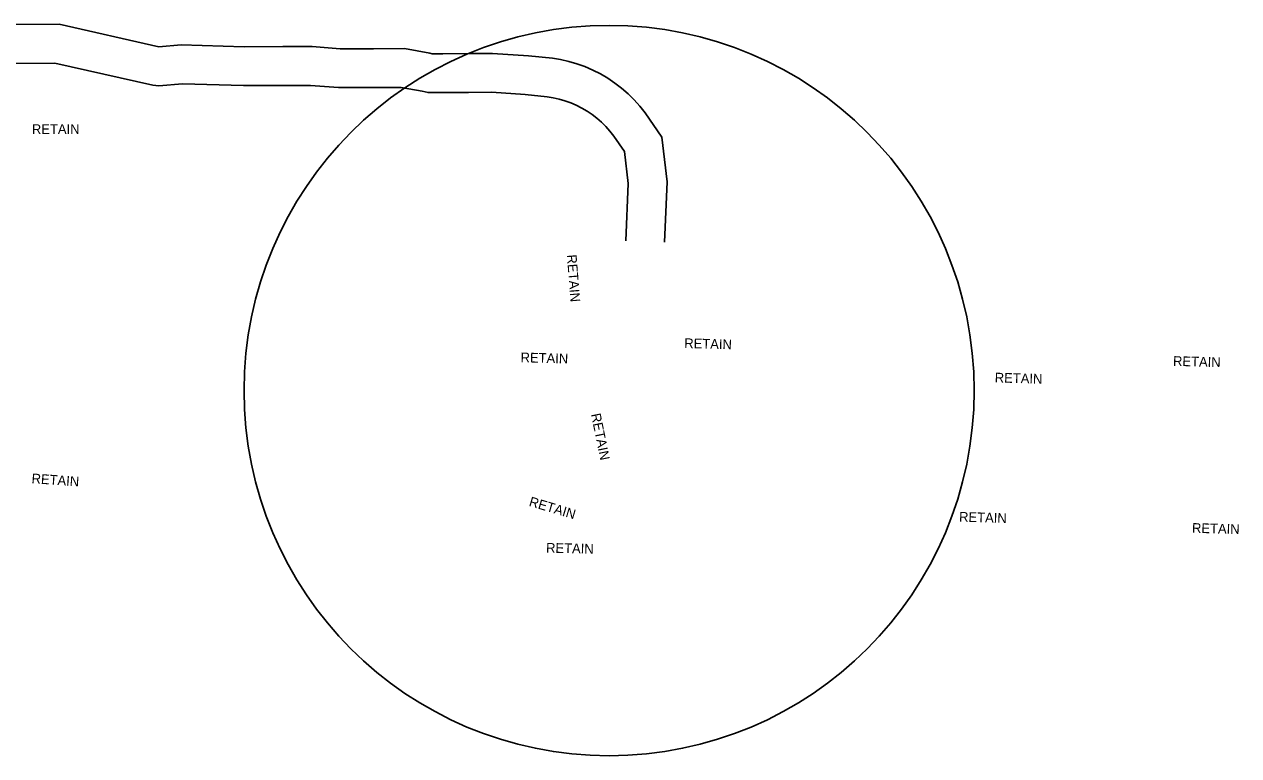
# Model space of a CAD drawing. Extents: x 2384780 to 2405432, y 547869 to 573706.
# Drawn here: x 2393192 to 2393817, y 552393 to 552769 of the extents above; entities that cross this region are included whole.
import ezdxf

# ---------------------------------------------------------------- set-up
doc = ezdxf.new("R2010")
doc.units = 0
for name, color, linetype in [('Old_Level_1', 7, 'Continuous'), ('Old_Level_63', 7, 'Continuous'), ('Prop Buffer Zone 1', 7, 'Continuous'), ('Prop Buffer Zone 2', 7, 'Continuous')]:
    doc.layers.add(name, color=color, linetype=linetype)

msp = doc.modelspace()

# ---------------------------------------------------------------- linework, layer by layer
at = {"layer": 'Old_Level_63'}
msp.add_circle((2393492.91, 552580.66), 187.94, dxfattribs=at)
at = {"layer": 'Prop Buffer Zone 1'}
for points in [[(2393141.45, 552748.9), (2393207.52, 552749.22)], [(2393207.52, 552749.22), (2393257.96, 552737.8)], [(2393501.46, 552657.8), (2393502.81, 552687.26), (2393500.77, 552703.79), (2393495.33, 552711.68), (2393493.38, 552714.16), (2393491.29, 552716.51), (2393489.05, 552718.73), (2393486.67, 552720.8), (2393484.18, 552722.73), (2393481.56, 552724.49), (2393478.85, 552726.09), (2393476.04, 552727.52), (2393473.14, 552728.77), (2393470.18, 552729.84), (2393467.16, 552730.72), (2393464.1, 552731.41), (2393461.11, 552731.89), (2393449.76, 552733.04), (2393432.3, 552734.23), (2393420.5, 552734.15), (2393407.44, 552734.03), (2393399.7, 552734.05), (2393396.68, 552734.72), (2393385.82, 552736.74), (2393371.76, 552736.59), (2393353.64, 552736.64), (2393339.23, 552737.69), (2393325, 552737.72), (2393304.76, 552737.62), (2393273.23, 552738.59), (2393261.05, 552737.53), (2393257.96, 552737.8)]]:
    msp.add_lwpolyline(points, dxfattribs=at)
at = {"layer": 'Prop Buffer Zone 2'}
for points in [[(2393143.25, 552768.89), (2393209.89, 552769.19), (2393261.07, 552757.6)], [(2393521.45, 552657.07), (2393522.87, 552688.03), (2393520.02, 552711.11), (2393511.44, 552723.55), (2393508.73, 552727.01), (2393505.8, 552730.28), (2393502.68, 552733.38), (2393499.37, 552736.27), (2393495.89, 552738.95), (2393492.25, 552741.41), (2393488.46, 552743.64), (2393484.54, 552745.63), (2393480.5, 552747.38), (2393476.37, 552748.86), (2393472.16, 552750.09), (2393467.91, 552751.05), (2393463.73, 552751.73), (2393451.45, 552752.98), (2393432.91, 552754.23), (2393420.34, 552754.15), (2393407.38, 552754.03), (2393401.9, 552754.05), (2393400.66, 552754.32), (2393387.56, 552756.76), (2393371.68, 552756.59), (2393354.39, 552756.64), (2393339.98, 552757.69), (2393324.98, 552757.72), (2393305.02, 552757.62), (2393272.67, 552758.62), (2393261.07, 552757.6)]]:
    msp.add_lwpolyline(points, dxfattribs=at)

# ---------------------------------------------------------------- texts
at = {"layer": 'Old_Level_1'}
for rotation, p in [(0.22299, (2393195.79, 552712.69)), (274.59445, (2393471.15, 552650.49)), (358.38067, (2393531.56, 552602.58)), (358.38067, (2393447.3, 552595.28)), (358.38067, (2393783.18, 552593.41)), (358.38067, (2393691.41, 552584.87)), (281.61462, (2393483.56, 552568.44)), (356.06799, (2393195.49, 552533.01)), (343.46289, (2393451.34, 552521.37)), (358.38067, (2393673.05, 552513.22)), (358.38067, (2393792.95, 552507.48)), (358.6428, (2393460.43, 552497.27))]:
    msp.add_text('RETAIN', height=5, rotation=rotation, dxfattribs=at).set_placement(p)

doc.saveas('drawing.dxf')
